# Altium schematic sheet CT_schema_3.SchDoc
size 298 x 247 mm
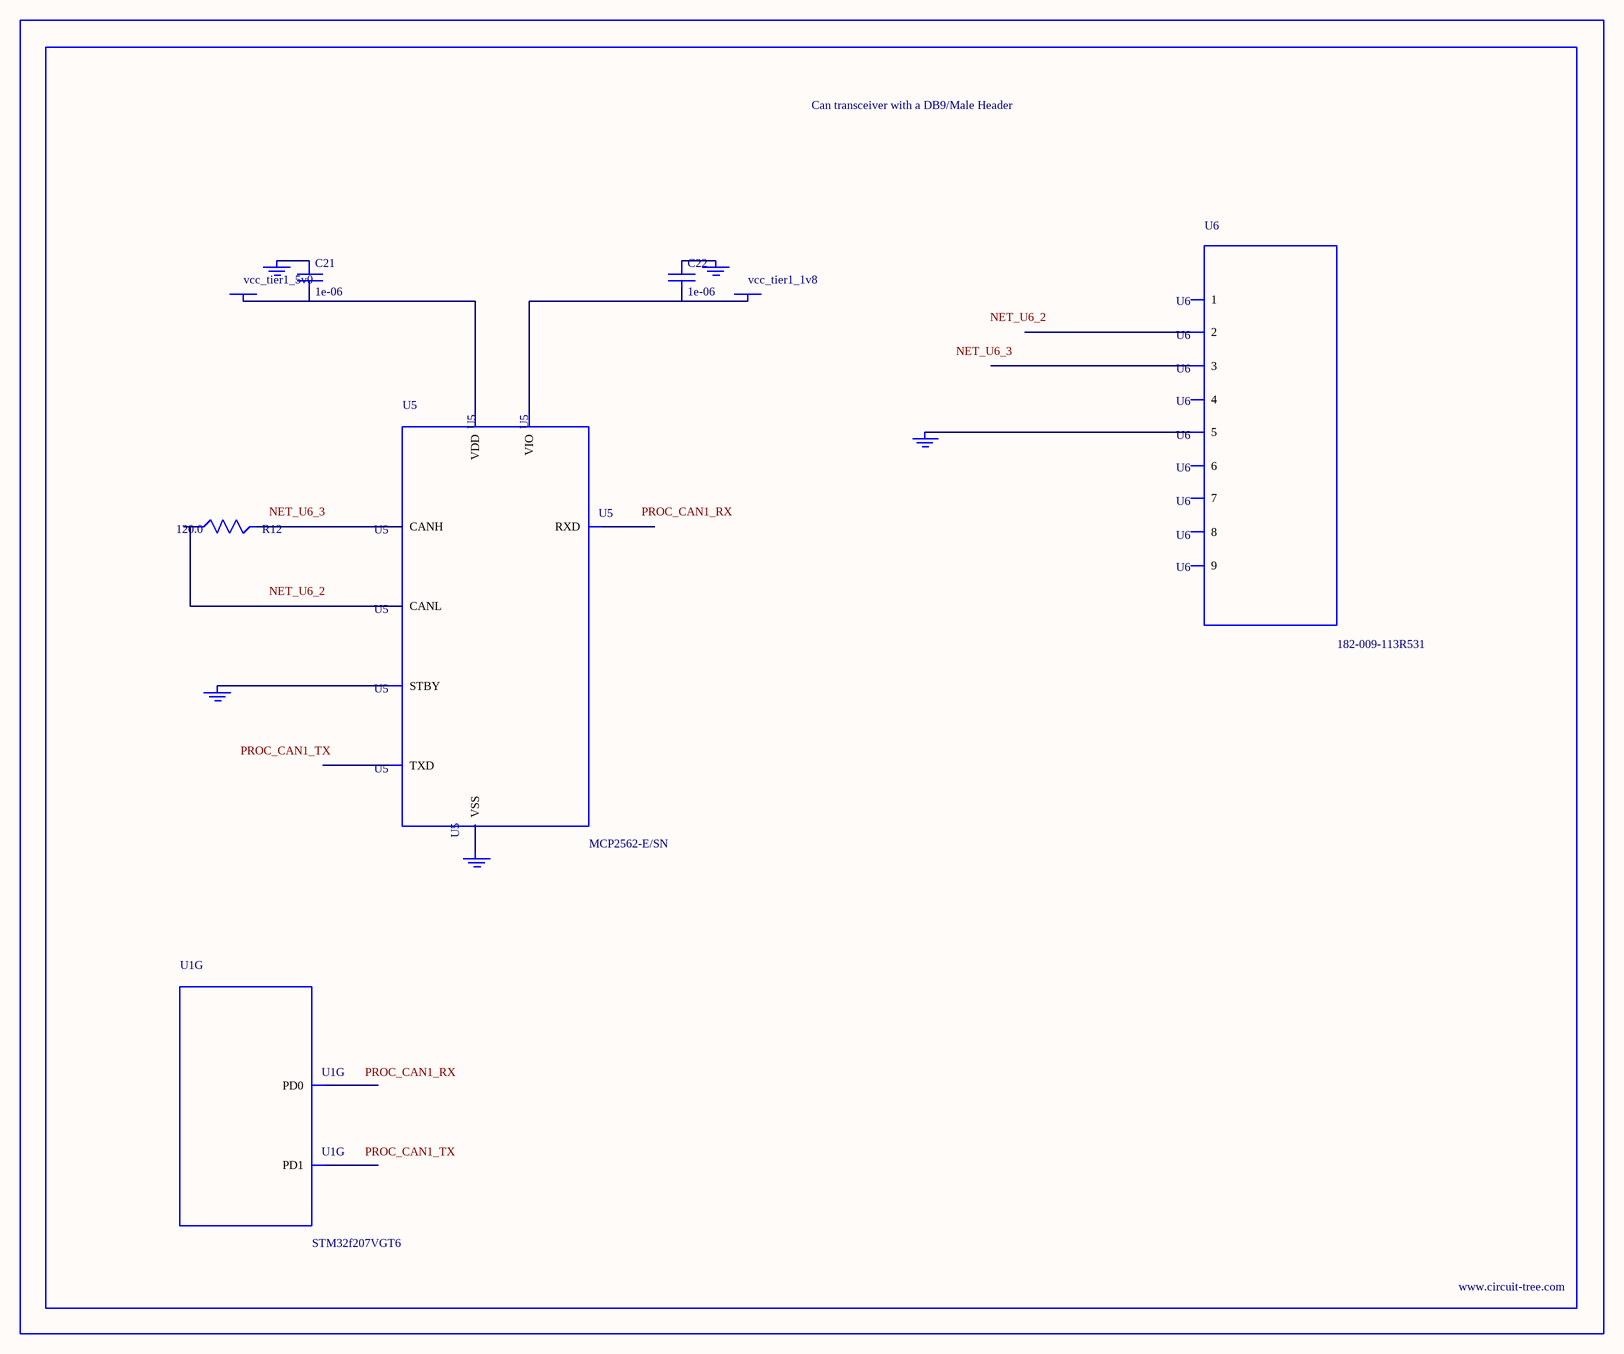
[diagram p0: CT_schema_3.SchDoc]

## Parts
BORDER2  (no value)
C21  1e-06  [C0603]
C22  1e-06  [C0603]
GND_INSTANCE_2_0  (no value)
GND_INSTANCE_2_1  (no value)
GND_INSTANCE_2_2  (no value)
GND_INSTANCE_2_3  (no value)
GND_INSTANCE_2_4  (no value)
POWER_INSTANCE_2_0  vcc_tier1_5v0
POWER_INSTANCE_2_1  vcc_tier1_1v8
R12  120.0  [R0603]
U1  STM32f207VGT6  [LQFP100]  (part G of 10)
U5  MCP2562-E/SN  [SOIC-8]
U6  182-009-113R531  [182-009-MALE]

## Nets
NetC21_1: C21.1 GND_INSTANCE_2_0.0(GND)
NetC21_2: C21.2 POWER_INSTANCE_2_0.0(PWR) U5.3(VDD)
NetC22_1: C22.1 GND_INSTANCE_2_1.0(GND)
NetC22_2: C22.2 POWER_INSTANCE_2_1.0(PWR) U5.5(VIO)
NetGND_INSTANCE_2_2_0: GND_INSTANCE_2_2.0(GND) U5.8(STBY)
NetGND_INSTANCE_2_3_0: GND_INSTANCE_2_3.0(GND) U5.2(VSS)
NetGND_INSTANCE_2_4_0: GND_INSTANCE_2_4.0(GND) U6.5
NetR12_1: R12.1 U5.6(CANL)
NetR12_2: R12.2 U5.7(CANH)

Not connected (* = marked no-connect by the designer): U1 81(PD0) 82(PD1); U5 1(TXD) 4(RXD); U6 1 2 3 4 6 7 8 9

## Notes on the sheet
- Labels drawn without touching a wire or pin: NET_U6_2, NET_U6_3, PROC_CAN1_RX, PROC_CAN1_TX

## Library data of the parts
BORDER2 = BORDER_PAGE2
C21 C22 = C0603C105K3RACTU
GND_INSTANCE_2_0-GND_INSTANCE_2_4 = GND
POWER_INSTANCE_2_0 POWER_INSTANCE_2_1 = PWR
R12 = RC0603JR-07120RL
